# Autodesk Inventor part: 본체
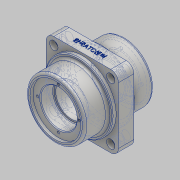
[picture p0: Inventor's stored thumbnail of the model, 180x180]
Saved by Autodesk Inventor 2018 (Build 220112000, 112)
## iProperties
Created: 2023-10
Part Number: 본체
Material: 알루미늄 6061
Document SubType Name: Modeling
Designer: home
Density: 2.7 g/cm^3
Appearance: 알루미늄 - 평지
Mass: 946.208 g
Surface Area: 537.857 cm^2
Volume: 350.447 cm^3
Author: home
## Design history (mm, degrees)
sketch "스케치1"
  geometry: L1 (37, -47)-(-37, -47); L2 (-47, -37)-(-47, 37); L3 (-37, 47)-(37, 47); L4 (47, 37)-(47, -37); L5 (47, -47)-(-47, 47); L6 (-47, -47)-(47, 47); C1 r 3.3 at (37, 37); C2 r 3.3 at (-37, 37); C3 r 3.3 at (-37, -37); C4 r 3.3 at (37, -37); A1 r 10 centre (37, -37) between (37, -47) and (47, -37); A2 r 10 centre (-37, -37) between (-47, -37) and (-37, -47); A3 r 10 centre (-37, 37) between (-37, 47) and (-47, 37); A4 r 10 centre (37, 37) between (47, 37) and (37, 47); 3 further points
  constraints: 12 end point, 8 centre point, 8 point on circle, 8 point on line, 8 tangent, 5 coincident, 3 equal radius, 3 midpoint, 2 parallel, 1 horizontal, 1 perpendicular
  dimensions: "d0" = 94 distance of L5.start L6.start; "d1" = 94 distance of L6.start L5.end; "d2" = 10 radius of A1; "d4" = 6.6 diameter of C1; "d5" = 6.6 diameter of C2; "d6" = 6.6 diameter of C3; "d7" = 6.6 diameter of C4
extrude "돌출1" new body sketch "스케치1" stored distance "d8" = 20; taper "d9" = 0 deg
sketch "스케치3"
  geometry: C1 r 3.3 at (-37, -37) reference; C2 r 5.5 at (-37, -37); C3 r 3.3 at (-37, 37) reference; C4 r 3.3 at (37, 37) reference; C5 r 3.3 at (37, -37) reference; C6 r 5.5 at (-37, 37); C7 r 5.5 at (37, 37); C8 r 5.5 at (37, -37); 1 further point
  constraints: 4 centre point, 4 coincident
  dimensions: "d16" = 11 diameter of C2; "d17" = 11 diameter of C6; "d18" = 11 diameter of C7; "d19" = 11 diameter of C8
extrude "돌출3" cut sketch "스케치3" distance "d20" = 7; taper "d21" = 0 deg
sketch "스케치4"
  geometry: C1 r 44 at (0, 0); 1 further point
  constraints: 1 centre point, 1 coincident
  dimensions: "d22" = 88 diameter of C1
extrude "돌출4" join sketch "스케치4" distance "d23" = 5; taper "d24" = 0 deg
sketch "스케치5"
  geometry: C1 r 38 at (0, 0); 1 further point
  constraints: 1 centre point, 1 coincident
  dimensions: "d25" = 76 diameter of C1
extrude "돌출5" join sketch "스케치5" distance "d26" = 30; taper "d27" = 0 deg
sketch "스케치6"
  geometry: L1 (0, -161.906)-(0, 161.906); L2 (-33, -45)-(-33, -41); L3 (-33, -41)-(-23.5, -41); L4 (-23.5, -41)-(-23.5, -24); L5 (-23.5, -24)-(-20.5, -24); L6 (-20.5, -24)-(-20.5, 24); L7 (-20.5, 24)-(-23.5, 24); L8 (-23.5, 24)-(-23.5, 41); L9 (-23.5, 41)-(-33, 41); L10 (-33, 41)-(-33, 45); L11 (-33, 45)-(0, 45); L12 (-33, -45)-(0, -45); L13 (0, -45)-(0, 45); 2 further points
  constraints: 26 end point, 8 perpendicular, 4 point on line, 2 vertical, 1 coincident, 1 collinear, 1 midpoint
  dimensions: "d39" = 66 diameter of L2 L1; "d40" = 47 diameter of L4 L1; "d41" = 47 diameter of L8 L1; "d42" = 41 diameter of L6 L1; "d43" = 45 distance from line of point (0, 0) L12; "d44" = 4 distance of L2.start L2.end; "d45" = 4 distance of L9.end L10.end; "d46" = 17 distance of L3.end L4.end; "d47" = 17 distance of L7.end L8.end; "d48" = 90 distance of L12.end L11.end; "d49" = 137.90625 distance from line of L1.end L7
revolve "회전1" sketch "스케치6" stored, may be unused: angle "d50" = 90 deg
sketch "스케치7"
  geometry: 2 further points
  constraints: 1 horizontal alignment
  dimensions: "d51" = 27 distance of point (0, 0) point (-27, 0)
hole "구멍1" sketch "스케치7" at (-27, 0) diameter "d52" = 3.242; stored, may be unused: countersink angle "d56" = 90 deg, drill point angle "d58" = 118 deg; dims "d53" = 8, "d54" = 4, "d55" = 2, "d57" = 10
sketch "스케치8"
  geometry: 2 further points
  constraints: 1 coincident
hole "구멍2" sketch "스케치8" at (-37, 10) diameter "d62" = 5.188; stored, may be unused: countersink angle "d66" = 90 deg, drill point angle "d68" = 118 deg; dims "d63" = 16, "d64" = 7, "d65" = 4, "d67" = 30
sketch "스케치9"
  geometry: C1 r 7 at (-37, 10); 1 further point
  constraints: 1 centre point, 1 coincident
  dimensions: "d69" = 14 diameter of C1
extrude "돌출6" cut sketch "스케치9" distance "d70" = 2; taper "d71" = 0 deg
fillet "모깎기1" dims "d72" = 3
sketch "스케치10"
  geometry: 2 further points
  constraints: 1 coincident, 1 other
feature "엠보싱1" sketch "스케치10" dims "d75" = 0.5, "d76" = 0
fillet "모깎기4" dims "d77" = 1
chamfer "모따기1" distance "d78" = 1; stored, may be unused: second distance "d79" = 2, angle "d80" = 45 deg
chamfer "모따기2" distance "d81" = 1; stored, may be unused: second distance "d82" = 2, angle "d83" = 45 deg
node "솔리드1"
mirror "미러1"
mirror "미러2"
pattern_circular "원형 패턴1" dims angle "d60" = 360 deg
mirror "미러3"
